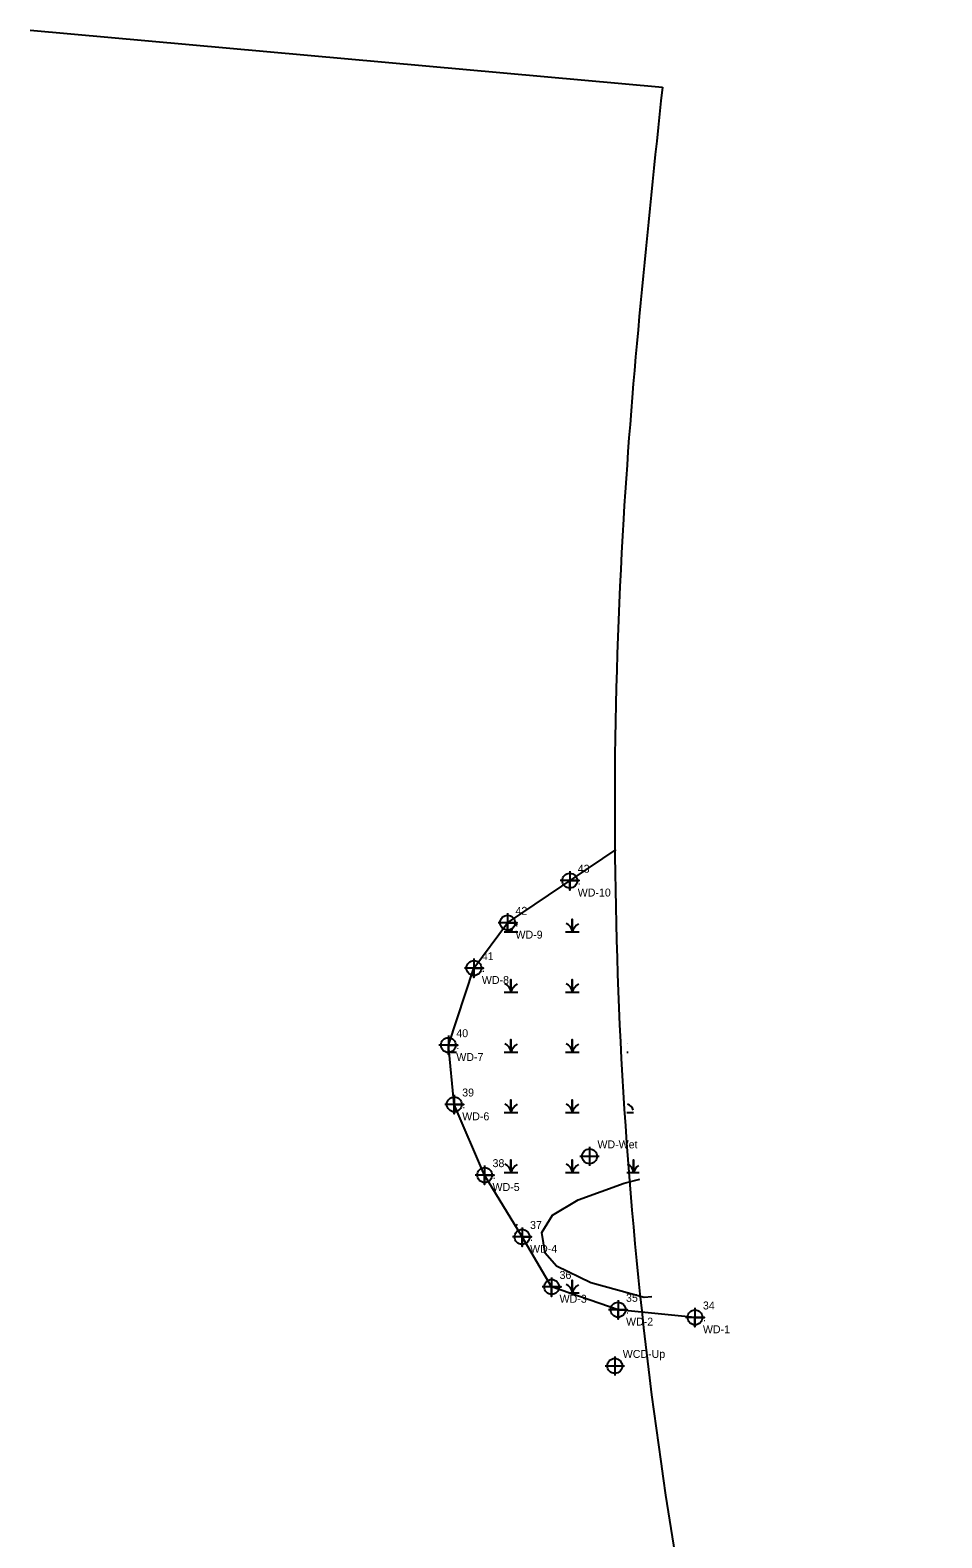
# Model space of a CAD drawing. Extents: x 1835303 to 1835785, y 366400 to 367935.
# Drawn here: x 1835423.5 to 1835710.7, y 367460.4 to 367935.3 of the extents above; entities that cross this region are included whole.
import ezdxf

# ---------------------------------------------------------------- set-up
doc = ezdxf.new("R2010")
doc.units = 0
for name, color, linetype in [('Cogo Default Point CELL', 7, 'Continuous'), ('COGO Default Point Number', 7, 'Continuous'), ('Default', 7, 'Continuous'), ('Exist Environmental Wetland Boundary', 7, 'Continuous'), ('Exist Environmental Wetland Boundary Cogo Comment', 7, 'Continuous'), ('Exist Environmental Wetland Boundary Cogo Elevation', 7, 'Continuous'), ('Exist Environmental Wetland Boundary Cogo Number', 7, 'Continuous'), ('Exist Environmental Wetland Boundary Cogo Point CELL', 7, 'Continuous'), ('Exist Hydro Jurisdictional Stream or Body of Water NEU Mitigable', 7, 'Continuous'), ('Exist Hydro Swamp or Marsh', 7, 'Continuous')]:
    doc.layers.add(name, color=color, linetype=linetype)

msp = doc.modelspace()

# ---------------------------------------------------------------- linework, layer by layer
at = {"layer": 'Cogo Default Point CELL'}
for points in [[(1835596.73, 367580.62), (1835599.73, 367580.62)], [(1835599.73, 367583.62), (1835599.73, 367580.62)], [(1835599.73, 367580.62), (1835602.73, 367580.62)], [(1835599.73, 367580.62), (1835599.73, 367577.62)], [(1835604.7, 367514.61), (1835607.7, 367514.61)], [(1835607.7, 367517.61), (1835607.7, 367514.61)], [(1835607.7, 367514.61), (1835610.7, 367514.61)], [(1835607.7, 367514.61), (1835607.7, 367511.61)]]:
    msp.add_lwpolyline(points, dxfattribs=at)
for centre in [(1835599.73, 367580.62), (1835607.7, 367514.61)]:
    msp.add_circle(centre, 2.34, dxfattribs=at)
at = {"layer": 'Default'}
msp.add_line((1835423.5, 367935.32), (1835622.69, 367917.35), dxfattribs=at)
msp.add_spline([(1835622.69, 367917.35), (1835610.42, 367781.31), (1835628.86, 367442.44), (1835700.95, 367057.13), (1835601.57, 366602.08), (1835470.17, 366400.05)], degree=3, dxfattribs=at)
at = {"layer": 'Exist Environmental Wetland Boundary'}
msp.add_lwpolyline([(1835632.96, 367529.87), (1835608.73, 367532.29), (1835587.8, 367539.49), (1835578.5, 367555.23), (1835566.68, 367574.7), (1835557.12, 367596.96), (1835555.26, 367615.63), (1835563.31, 367639.9), (1835573.91, 367654.18), (1835608.1, 367677.3)], dxfattribs=at)
at = {"layer": 'Exist Environmental Wetland Boundary Cogo Point CELL'}
for points in [[(1835593.52, 367670.44), (1835593.52, 367664.44), (1835593.52, 367667.44), (1835596.52, 367667.44), (1835590.52, 367667.44)], [(1835573.91, 367657.18), (1835573.91, 367651.18), (1835573.91, 367654.18), (1835576.91, 367654.18), (1835570.91, 367654.18)], [(1835563.31, 367642.9), (1835563.31, 367636.9), (1835563.31, 367639.9), (1835566.31, 367639.9), (1835560.31, 367639.9)], [(1835555.26, 367618.63), (1835555.26, 367612.63), (1835555.26, 367615.63), (1835558.26, 367615.63), (1835552.26, 367615.63)], [(1835557.12, 367599.96), (1835557.12, 367593.96), (1835557.12, 367596.96), (1835560.12, 367596.96), (1835554.12, 367596.96)], [(1835566.68, 367577.7), (1835566.68, 367571.7), (1835566.68, 367574.7), (1835569.68, 367574.7), (1835563.68, 367574.7)], [(1835578.5, 367558.23), (1835578.5, 367552.23), (1835578.5, 367555.23), (1835581.5, 367555.23), (1835575.5, 367555.23)], [(1835587.8, 367542.49), (1835587.8, 367536.49), (1835587.8, 367539.49), (1835590.8, 367539.49), (1835584.8, 367539.49)], [(1835608.73, 367535.29), (1835608.73, 367529.29), (1835608.73, 367532.29), (1835611.73, 367532.29), (1835605.73, 367532.29)], [(1835632.96, 367532.87), (1835632.96, 367526.87), (1835632.96, 367529.87), (1835635.96, 367529.87), (1835629.96, 367529.87)]]:
    msp.add_lwpolyline(points, dxfattribs=at)
for centre in [(1835593.52, 367667.44), (1835573.91, 367654.18), (1835563.31, 367639.9), (1835555.26, 367615.63), (1835557.12, 367596.96), (1835566.68, 367574.7), (1835578.5, 367555.23), (1835587.8, 367539.49), (1835608.73, 367532.29), (1835632.96, 367529.87)]:
    msp.add_circle(centre, 2.34, dxfattribs=at)
at = {"layer": 'Exist Hydro Jurisdictional Stream or Body of Water NEU Mitigable'}
msp.add_lwpolyline([(1835619.32, 367536.3), (1835616.96, 367536.16), (1835600.11, 367540.79), (1835589.37, 367546.06), (1835585.79, 367550.06), (1835584.73, 367556.59), (1835588.1, 367562.07), (1835596.11, 367566.92), (1835610.64, 367572.18), (1835615.53, 367573.41)], dxfattribs=at)
at = {"layer": 'Exist Hydro Swamp or Marsh'}
for points in [[(1835573.91, 367651.31), (1835574.98, 367651.31), (1835574.98, 367652.12)], [(1835574.98, 367652.12), (1835574.98, 367651.31), (1835577.13, 367651.31)], [(1835592.14, 367651.31), (1835594.29, 367651.31), (1835594.29, 367655.26), (1835594.29, 367651.31), (1835596.44, 367651.31)], [(1835572.83, 367651.31), (1835573.91, 367651.31)], [(1835572.83, 367632.36), (1835574.98, 367632.36), (1835574.98, 367636.31), (1835574.98, 367632.36), (1835577.13, 367632.36)], [(1835592.14, 367632.36), (1835594.29, 367632.36), (1835594.29, 367636.31), (1835594.29, 367632.36), (1835596.44, 367632.36)], [(1835555.92, 367613.41), (1835557.82, 367613.41)], [(1835572.83, 367613.41), (1835574.98, 367613.41), (1835574.98, 367617.36), (1835574.98, 367613.41), (1835577.13, 367613.41)], [(1835592.14, 367613.41), (1835594.29, 367613.41), (1835594.29, 367617.36), (1835594.29, 367613.41), (1835596.44, 367613.41)], [(1835611.46, 367613.41), (1835611.93, 367613.41)], [(1835572.83, 367594.46), (1835574.98, 367594.46), (1835574.98, 367598.41), (1835574.98, 367594.46), (1835577.13, 367594.46)], [(1835592.14, 367594.46), (1835594.29, 367594.46), (1835594.29, 367598.41), (1835594.29, 367594.46), (1835596.44, 367594.46)], [(1835611.46, 367594.46), (1835613.55, 367594.46)], [(1835572.83, 367575.51), (1835574.98, 367575.51), (1835574.98, 367579.46), (1835574.98, 367575.51), (1835577.13, 367575.51)], [(1835592.14, 367575.51), (1835594.29, 367575.51), (1835594.29, 367579.46), (1835594.29, 367575.51), (1835596.44, 367575.51)], [(1835611.46, 367575.51), (1835613.61, 367575.51), (1835613.61, 367579.46), (1835613.61, 367575.51), (1835615.33, 367575.51)], [(1835593.26, 367537.61), (1835594.29, 367537.61), (1835594.29, 367541.56), (1835594.29, 367537.61), (1835596.44, 367537.61)], [(1835611.46, 367537.61), (1835611.68, 367537.61)]]:
    msp.add_lwpolyline(points, dxfattribs=at)
for centre, radius, start, end in [((1835571.92, 367651.09), 3.07, 4.1403, 17.8588), ((1835579.54, 367649.8), 4.81, 122.1274, 161.6222), ((1835591.23, 367651.09), 3.07, 4.1403, 67.535), ((1835598.86, 367649.8), 4.81, 122.1274, 161.6222), ((1835571.92, 367632.14), 3.07, 4.1403, 67.535), ((1835579.54, 367630.85), 4.81, 122.1274, 161.6222), ((1835591.23, 367632.14), 3.07, 4.1403, 67.535), ((1835598.86, 367630.85), 4.81, 122.1274, 161.6222), ((1835560.23, 367611.9), 4.81, 122.1274, 123.5298), ((1835571.92, 367613.19), 3.07, 4.1403, 67.535), ((1835579.54, 367611.9), 4.81, 122.1274, 161.6222), ((1835591.23, 367613.19), 3.07, 4.1403, 67.535), ((1835598.86, 367611.9), 4.81, 122.1274, 161.6222), ((1835610.54, 367613.19), 3.07, 67.4934, 67.535), ((1835571.92, 367594.24), 3.07, 4.1403, 67.535), ((1835579.54, 367592.95), 4.81, 122.1274, 161.6222), ((1835591.23, 367594.24), 3.07, 4.1403, 67.535), ((1835598.86, 367592.95), 4.81, 122.1274, 161.6222), ((1835610.54, 367594.24), 3.07, 16.2762, 67.535), ((1835571.92, 367575.29), 3.07, 4.1403, 67.535), ((1835579.54, 367574), 4.81, 122.1274, 161.6222), ((1835591.23, 367575.29), 3.07, 4.1403, 67.535), ((1835598.86, 367574), 4.81, 122.1274, 161.6222), ((1835610.54, 367575.29), 3.07, 4.1403, 67.535), ((1835618.17, 367574), 4.81, 129.4645, 161.6222), ((1835579.54, 367555.05), 4.81, 122.1274, 130.8263), ((1835591.23, 367537.39), 3.07, 4.1403, 67.535), ((1835598.86, 367536.1), 4.81, 122.1274, 161.6222)]:
    msp.add_arc(centre, radius, start, end, dxfattribs=at)

# ---------------------------------------------------------------- texts
at = {"layer": 'COGO Default Point Number'}
for s, p in [('WD-Wet', (1835602.23, 367583.12)), ('WCD-Up', (1835610.2, 367517.11))]:
    msp.add_text(s, height=2.5, dxfattribs=at).set_placement(p)
at = {"layer": 'Exist Environmental Wetland Boundary Cogo Comment'}
for s, p in [('WD-10', (1835596.02, 367662.44)), ('WD-9', (1835576.41, 367649.18)), ('WD-8', (1835565.81, 367634.9)), ('WD-7', (1835557.76, 367610.63)), ('WD-6', (1835559.62, 367591.96)), ('WD-5', (1835569.18, 367569.7)), ('WD-4', (1835581, 367550.23)), ('WD-3', (1835590.3, 367534.49)), ('WD-2', (1835611.23, 367527.29)), ('WD-1', (1835635.46, 367524.88))]:
    msp.add_text(s, height=2.5, dxfattribs=at).set_placement(p)
at = {"layer": 'Exist Environmental Wetland Boundary Cogo Elevation'}
for p in [(1835596.02, 367666.19), (1835576.41, 367652.93), (1835565.81, 367638.65), (1835557.76, 367614.38), (1835559.62, 367595.71), (1835569.18, 367573.45), (1835581, 367553.98), (1835590.3, 367538.24), (1835611.23, 367531.04), (1835635.46, 367528.62)]:
    msp.add_text('.', height=2.5, dxfattribs=at).set_placement(p)
at = {"layer": 'Exist Environmental Wetland Boundary Cogo Number'}
for s, p in [('43', (1835596.02, 367669.94)), ('42', (1835576.41, 367656.68)), ('41', (1835565.81, 367642.4)), ('40', (1835557.76, 367618.13)), ('39', (1835559.62, 367599.46)), ('38', (1835569.18, 367577.2)), ('37', (1835581, 367557.73)), ('36', (1835590.3, 367541.99)), ('35', (1835611.23, 367534.79)), ('34', (1835635.46, 367532.38))]:
    msp.add_text(s, height=2.5, dxfattribs=at).set_placement(p)

doc.saveas('drawing.dxf')
